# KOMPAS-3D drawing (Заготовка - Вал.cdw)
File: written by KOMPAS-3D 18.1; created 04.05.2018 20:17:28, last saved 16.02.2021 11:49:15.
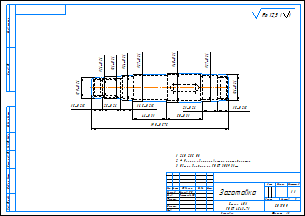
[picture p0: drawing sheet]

Sheet 1: A3, landscape

Title block, sheet 1: name: Заготовка; material: Сталь 40Х / ГОСТ 4543-71; scale: 1:1; sheets: 1; sheet format: A3; stored path: C:\Users\alan\Desktop\Вал.cdw; drawn by: Маяков Р.В.; checked by: Хрусталева И.Н.

Views: Вид 1, Вид 2, Выносной элемент 4, Выносной элемент 5, Выносной элемент 6
Referenced files in C:\Users\rusla\AppData\Local\Temp\: KPSF192.tmp
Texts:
  260...285 HB.
  * Размер обеспечивается инструментом.
  Общие допуски по ГОСТ 30893.1-т
  Ra 12,5
  Ra 12,5 ( )
  Стили документа
  СПбГПУ
  Материал-Предприятие
  Лит-Масса-Масштаб
  Масштаб
  Изм.
  Лист
  № докум.
  Подп.
  Дата
  Лит.
  Разраб.
  Пров.
  Т.контр.
  Листов
  Н.контр.
  Утв.
  Изменение
  Номер документа
  Подпись
  Обозначение документа
  Наименование изделия
  Масса изделия по ГОСТ 2.109-73
  Порядковый номер листа
  Общее количество листов в документе
  Характер работы, выполненной лицом, подписавшим документ
  Наименование или индекс предприятия, выпускающего документ
  Инв. № подл.
  Подп. и дата
  Взам. инв. №
  Инв. № дубл.
  Инвентарный номер подлинника по ГОСТ 2.501-2013
  Подпись принявшего подлинник в отдел технической документации
  Инвентарный номер подлинника, взамен которого выпущен данный подлинник
  Инвентарный номер дубликата по ГОСТ 2.502-2013
  Подпись принявшего дубликат в отдел технической документации
  Справ. №
  Перв. примен.
  Обозначение документа, взамен или на основании которого выпущен данный документ
  Обозначение документа, в котором впервые записан данный документ
  Подпись лица, копировавшего чертеж
  Обозначение формата листа
Dimensions and other numbers on the sheet: 190±0,575; 15±0,215; 25; 46±0,31; 50; 21±0,26; 29±0,26; 31±0,31; 26±0,26; 34±0,31; 37±0,31; 40±0,31; 36±0,31; 16,5±0,215; 1:1; 1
